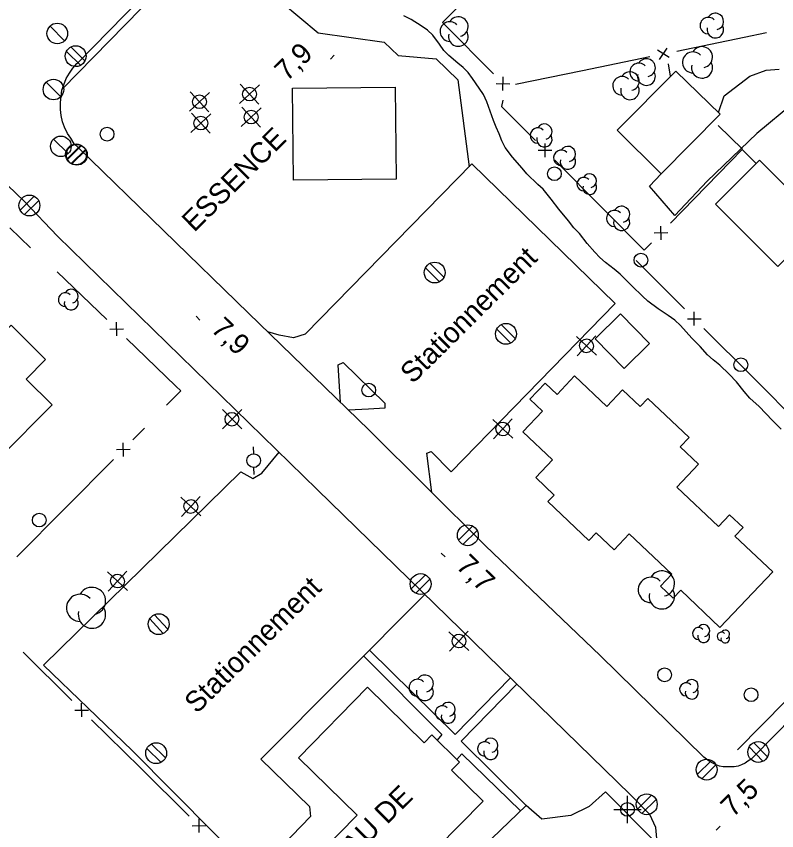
# Model space of a CAD drawing. Extents: x 381879 to 384696, y 5564785 to 5567594.
# Drawn here: x 382976.2 to 383086.9, y 5565460.7 to 5565579.4 of the extents above; entities that cross this region are included whole.
import ezdxf

# ---------------------------------------------------------------- set-up
doc = ezdxf.new("R2010")
doc.units = 0
for name, color, linetype in [('Niveau 19', 7, 'Continuous'), ('Niveau 2', 7, 'Continuous'), ('Niveau 21', 7, 'Continuous'), ('Niveau 22', 7, 'Continuous'), ('Niveau 3', 7, 'Continuous'), ('Niveau 31', 7, 'Continuous'), ('Niveau 36', 7, 'Continuous'), ('Niveau 37', 7, 'Continuous'), ('Niveau 44', 7, 'Continuous'), ('Niveau 52', 7, 'Continuous')]:
    doc.layers.add(name, color=color, linetype=linetype)

msp = doc.modelspace()

# ---------------------------------------------------------------- linework, layer by layer
at = {"layer": 'Niveau 19'}
for points in [[(383004.09, 5565590.45), (383020.14, 5565576.98), (383029.75, 5565575.6), (383031.78, 5565573.66), (383037.3, 5565573.18), (383040.47, 5565570.14), (383042.11, 5565557.46)], [(383078.43, 5565565.36), (383079.25, 5565567.78), (383082.99, 5565570.67), (383085.4, 5565571.55), (383087.27, 5565571.69)], [(383089.4, 5565566.79), (383084.03, 5565562.31), (383076.8, 5565555.33), (383072.08, 5565550.36), (383068.41, 5565554.6), (383070.1, 5565556.4)]]:
    msp.add_lwpolyline(points, dxfattribs=at)
at = {"layer": 'Niveau 2'}
msp.add_lwpolyline([(383087.58, 5565519.2), (383086.3, 5565520.48), (383084.35, 5565522.49), (383083, 5565523.74), (383082.17, 5565524.68), (383081.04, 5565526.09), (383079.99, 5565527.24), (383078.64, 5565528.53), (383077.64, 5565529.32), (383076.85, 5565530.05), (383075.75, 5565531.25), (383074.55, 5565532.49), (383072.89, 5565534.31), (383072.06, 5565535.07), (383071.12, 5565535.77), (383069.63, 5565536.74), (383068.15, 5565537.87), (383067.38, 5565538.58), (383065.87, 5565540.04), (383064.12, 5565541.79), (383063.24, 5565542.53), (383061.96, 5565543.5), (383061.16, 5565544.21), (383060.43, 5565544.99), (383059.31, 5565546.29), (383058.19, 5565547.71), (383057.39, 5565548.57), (383056.6, 5565549.56), (383055.17, 5565551.26), (383054.08, 5565552.72), (383052.92, 5565554.17), (383052.14, 5565554.89), (383050.53, 5565556.43), (383049.82, 5565557.23), (383048.43, 5565558.86), (383047.37, 5565560.24), (383046.88, 5565561.22), (383046.5, 5565562.26), (383046.05, 5565563.23), (383045.69, 5565564.21), (383044.7, 5565566.93), (383044.22, 5565568), (383043.56, 5565568.89), (383042.62, 5565570.31), (383041.98, 5565571.19), (383041.27, 5565571.94), (383040.48, 5565572.56), (383039.15, 5565573.69), (383038.44, 5565574.41), (383037.81, 5565575.31), (383036.82, 5565576.64), (383036.04, 5565577.38), (383035.13, 5565578), (383033.66, 5565578.94), (383032.61, 5565579.45)], dxfattribs=at)
at = {"layer": 'Niveau 21'}
for points in [[(382985.1, 5565572.6), (383001, 5565588.9), (383017.9, 5565606.2), (383037.5, 5565626.2), (383057, 5565646.4), (383075.1, 5565664.5), (383092, 5565682.1), (383100.4, 5565690.4)], [(382879.6, 5565647.04), (382958.64, 5565570.33), (382977.34, 5565552.41)], [(382985.2, 5565560.2), (382984.6, 5565560.8), (382984.1, 5565561.6), (382983.6, 5565562.3), (382983.2, 5565563.2), (382982.9, 5565564), (382982.7, 5565564.9), (382982.6, 5565565.8), (382982.6, 5565566.8), (382982.7, 5565567.7), (382982.8, 5565568.6), (382983.1, 5565569.4), (382983.4, 5565570.3), (382983.9, 5565571.1), (382984.4, 5565571.8), (382985, 5565572.5), (382985.1, 5565572.6)], [(383076.3, 5565471.4), (383061.2, 5565486.2), (383044.5, 5565502.2), (383027.5, 5565519.1), (383010, 5565536.1), (382985.2, 5565560.2)], [(383065.57, 5565453.03), (383068.81, 5565456.41), (383069.5, 5565458.99), (383069.32, 5565461.15), (383068.44, 5565463.02), (383065.61, 5565465.9), (383019.96, 5565510.43), (382982.18, 5565547.34), (382977.34, 5565552.41)], [(383105.1, 5565493.3), (383095.1, 5565483.2), (383083.6, 5565471.5)], [(383083.6, 5565471.5), (383083.2, 5565471.1), (383082.7, 5565470.8), (383082.3, 5565470.5), (383081.8, 5565470.3), (383081.3, 5565470.1), (383080.7, 5565470), (383080.2, 5565470), (383079.7, 5565470), (383079.1, 5565470), (383078.6, 5565470.1), (383078.1, 5565470.3), (383077.6, 5565470.5), (383077.1, 5565470.8), (383076.7, 5565471.1), (383076.3, 5565471.4)]]:
    msp.add_lwpolyline(points, dxfattribs=at)
at = {"layer": 'Niveau 22'}
for points in [[(383103.6, 5565691.84), (383085.8, 5565673.75), (383067.78, 5565655.57), (382982.85, 5565568.74)], [(383048.14, 5565482.94), (383040.06, 5565474.72), (383027.62, 5565486.99)], [(383026.76, 5565486.13), (383038.15, 5565474.71), (383037.44, 5565473.87)], [(383050.4, 5565464.35), (383040.96, 5565473.75), (383049.05, 5565482.05)], [(383040.32, 5565471.04), (383041.06, 5565471.89), (383049.61, 5565463.59)]]:
    msp.add_lwpolyline(points, dxfattribs=at)
at = {"layer": 'Niveau 3'}
for p, q in [((383021.91, 5565573.15), (383022.48, 5565573.72)), ((383002.34, 5565535.66), (383002.91, 5565535.09)), ((383038.05, 5565501.15), (383038.62, 5565500.59)), ((383078.09, 5565460.77), (383078.66, 5565461.34))]:
    msp.add_line(p, q, dxfattribs=at)
at = {"layer": 'Niveau 31'}
for points in [[(383072.2, 5565571.4), (383078.7, 5565565.1), (383070.1, 5565556.4), (383063.7, 5565562.8)], [(383016.4, 5565568.91), (383031.36, 5565569.05), (383031.49, 5565555.63), (383016.53, 5565555.49)], [(383078, 5565552), (383084.4, 5565558.4), (383093.5, 5565549.3), (383087.1, 5565542.9)], [(382957.38, 5565531.49), (382973.88, 5565515.19), (382981.36, 5565522.76), (382977.59, 5565526.49), (382980.43, 5565529.36), (382975.4, 5565534.34), (382972.07, 5565530.97), (382964.38, 5565538.57)], [(383064.72, 5565528.06), (383060.47, 5565532.35), (383064.15, 5565536), (383068.4, 5565531.71)], [(383063.25, 5565501.64), (383060.64, 5565504.1), (383059.56, 5565502.97), (383053.58, 5565508.64), (383054.49, 5565509.6), (383051.82, 5565512.14), (383054.27, 5565514.72), (383049.94, 5565518.84), (383052.79, 5565521.84), (383050.95, 5565523.58), (383053.18, 5565525.93), (383054.92, 5565524.28), (383057.48, 5565526.97), (383062.18, 5565522.51), (383064.47, 5565524.92), (383067.02, 5565522.5), (383068.14, 5565523.68), (383074.15, 5565517.97), (383072.87, 5565516.63), (383075.54, 5565514.1), (383072.37, 5565510.76), (383078.44, 5565505), (383080.06, 5565506.71), (383082.02, 5565504.86), (383080.84, 5565503.62), (383086.33, 5565498.41), (383078.63, 5565490.31), (383072.93, 5565495.72), (383071.83, 5565494.55), (383069.97, 5565496.3), (383071.64, 5565498.06), (383065.44, 5565503.95)], [(383027.32, 5565481.58), (383035.55, 5565473.49), (383036.67, 5565474.63), (383040.71, 5565470.66), (383039.57, 5565469.5), (383044.17, 5565464.98), (383034.08, 5565454.72), (383029.62, 5565459.11), (383028.96, 5565458.44), (383034.92, 5565452.57), (383032.45, 5565450.06), (383033.78, 5565448.75), (383031.69, 5565446.62), (383030.49, 5565447.79), (383024.03, 5565441.17), (383014.15, 5565450.82), (383018.48, 5565455.25), (383016.45, 5565457.23), (383018.61, 5565459.44), (383020.54, 5565457.55), (383025.8, 5565462.93), (383017.26, 5565471.28)]]:
    msp.add_lwpolyline(points, close=True, dxfattribs=at)
at = {"layer": 'Niveau 36'}
for p, q in [((382983.2, 5565575.82), (382981.08, 5565577.94)), ((382983.46, 5565574.24), (382985.54, 5565572.22)), ((382986.16, 5565572.9), (382984.08, 5565574.92)), ((382982.64, 5565567.65), (382980.52, 5565569.77)), ((383011.48, 5565566.57), (383008.76, 5565569.49)), ((383001.37, 5565565.56), (383004.29, 5565568.28)), ((383004.19, 5565565.46), (383001.47, 5565568.38)), ((383008.66, 5565566.67), (383011.58, 5565569.39)), ((383008.9, 5565563.32), (383011.82, 5565566.04)), ((383011.72, 5565563.22), (383009, 5565566.14)), ((383001.57, 5565562.44), (383004.49, 5565565.16)), ((383004.39, 5565562.34), (383001.67, 5565565.26)), ((382983.72, 5565559.37), (382981.6, 5565561.49)), ((382985.56, 5565560.59), (382983.5, 5565558.55)), ((382985.66, 5565560.54), (382983.6, 5565558.5)), ((382984.16, 5565557.91), (382986.22, 5565559.95)), ((382984.26, 5565557.86), (382986.32, 5565559.9)), ((382978.76, 5565553.15), (382976.7, 5565551.11)), ((382977.36, 5565550.47), (382979.42, 5565552.51)), ((383038.44, 5565541.35), (383036.39, 5565543.4)), ((383035.76, 5565542.73), (383037.81, 5565540.68)), ((383048.83, 5565532.41), (383046.76, 5565534.44)), ((383046.13, 5565533.77), (383048.2, 5565531.74)), ((383057.74, 5565532.71), (383060.65, 5565529.99)), ((383057.84, 5565529.9), (383060.56, 5565532.81)), ((383008.99, 5565522.05), (383006.17, 5565519.23)), ((383008.99, 5565519.23), (383006.17, 5565522.05)), ((383045.55, 5565520.59), (383048.46, 5565517.87)), ((383045.65, 5565517.78), (383048.37, 5565520.69)), ((383010.66, 5565516.62), (383010.71, 5565515.62)), ((383010.81, 5565512.62), (383010.77, 5565513.62)), ((383000.11, 5565509.29), (383003.02, 5565506.57)), ((383000.21, 5565506.48), (383002.93, 5565509.39)), ((383042.61, 5565505.08), (383040.55, 5565503.04)), ((383041.21, 5565502.4), (383043.27, 5565504.44)), ((382989.43, 5565498.42), (382992.34, 5565495.7)), ((382989.53, 5565495.61), (382992.25, 5565498.52)), ((383035.74, 5565497.97), (383033.68, 5565495.93)), ((383034.34, 5565495.29), (383036.4, 5565497.33)), ((382995.59, 5565491.55), (382997.54, 5565489.4)), ((382998.21, 5565490.03), (382996.26, 5565492.18)), ((383039.17, 5565489.68), (383042.08, 5565486.96)), ((383039.27, 5565486.87), (383041.99, 5565489.78)), ((382997.88, 5565471.3), (382995.82, 5565473.34)), ((383085.56, 5565471.44), (383083.56, 5565473.53)), ((382995.18, 5565472.68), (382997.24, 5565470.64)), ((383082.9, 5565472.88), (383084.9, 5565470.79)), ((383077.4, 5565470.92), (383075.34, 5565468.88)), ((383076, 5565468.24), (383078.06, 5565470.28)), ((383065.16, 5565461.79), (383065.18, 5565465.78)), ((383068.68, 5565465.87), (383066.62, 5565463.83)), ((383067.28, 5565463.19), (383069.34, 5565465.23)), ((383063.18, 5565463.79), (383067.16, 5565463.78))]:
    msp.add_line(p, q, dxfattribs=at)
for centre, radius in [((382982.13, 5565576.88), 1.5), ((382981.57, 5565568.71), 1.5), ((383010.13, 5565568.04), 1), ((383002.84, 5565566.93), 1), ((383003.04, 5565563.81), 1), ((383010.37, 5565564.69), 1), ((382989.39, 5565562.2), 1), ((382982.65, 5565560.43), 1.5), ((382984.87, 5565559.25), 1.52), ((382984.97, 5565559.2), 1.52), ((383054.54, 5565556.43), 1), ((382978.07, 5565551.81), 1.52), ((383067.14, 5565543.84), 1), ((383081.69, 5565528.6), 1), ((383027.49, 5565524.9), 1), ((383007.57, 5565520.64), 1), ((382979.51, 5565505.96), 1), ((383041.92, 5565503.74), 1.52), ((383035.05, 5565496.63), 1.52), ((383070.59, 5565483.4), 1), ((383083.19, 5565480.5), 1), ((383076.71, 5565469.58), 1.52), ((383067.99, 5565464.53), 1.52), ((383065.18, 5565463.79), 1)]:
    msp.add_circle(centre, radius, dxfattribs=at)
for centre, major_axis, ratio in [((382984.81, 5565573.58), (-0.01, -1.52), 0.999981), ((383037.1, 5565542.03), (0.01, 1.52), 0.999981), ((383047.48, 5565533.1), (-0.02, -1.52), 0.999984), ((383059.21, 5565531.35), (-0.048, -0.999), 0.999982), ((383047.02, 5565519.23), (-0.048, -0.999), 0.999982), ((383010.74, 5565514.63), (-0.05, -0.999), 0.999983), ((383001.58, 5565507.93), (-0.048, -0.999), 0.999982), ((382990.9, 5565497.06), (-0.048, -0.999), 0.999982), ((382996.9, 5565490.78), (0.02, 1.52), 0.999983), ((383040.64, 5565488.32), (-0.048, -0.999), 0.999982), ((382996.53, 5565471.98), (0.01, 1.52), 0.999981), ((383084.23, 5565472.15), (-0.01, -1.52), 0.999983)]:
    msp.add_ellipse(centre, major_axis=major_axis, ratio=ratio, dxfattribs=at)
at = {"layer": 'Niveau 37'}
for p, q in [((383071.24, 5565573.37), (383069.57, 5565574.47)), ((383069.86, 5565573.08), (383070.96, 5565574.75)), ((383046.05, 5565569.57), (383048.05, 5565569.55)), ((383047.04, 5565568.56), (383047.06, 5565570.56)), ((383053.18, 5565558.85), (383053.19, 5565560.85)), ((383052.18, 5565559.85), (383054.18, 5565559.85)), ((383070.08, 5565546.79), (383070.05, 5565548.79)), ((383071.06, 5565547.81), (383069.06, 5565547.78)), ((383074.91, 5565534.31), (383074.91, 5565536.31)), ((383073.91, 5565535.31), (383075.91, 5565535.31)), ((382990.79, 5565532.8), (382990.75, 5565534.8)), ((382989.77, 5565533.78), (382991.77, 5565533.82)), ((382991.75, 5565515.22), (382991.74, 5565517.22)), ((382992.74, 5565516.22), (382990.74, 5565516.21)), ((382985.7, 5565477.26), (382985.68, 5565479.26)), ((382984.69, 5565478.25), (382986.69, 5565478.27)), ((383001.78, 5565461.41), (383003.79, 5565461.42)), ((383002.79, 5565460.41), (383002.78, 5565462.41))]:
    msp.add_line(p, q, dxfattribs=at)
for points in [[(383044.91, 5565585.21), (383038.25, 5565578.5), (383038.63, 5565578.11)], [(383038.63, 5565578.11), (383045.65, 5565570.98)], [(383082.16, 5565576.34), (383085.43, 5565577.01)], [(383072.37, 5565574.32), (383082.16, 5565576.34)], [(383058.65, 5565571.5), (383068.45, 5565573.51)], [(383071.45, 5565570.64), (383071.16, 5565572.43)], [(383048.86, 5565569.48), (383058.65, 5565571.5)], [(383047.03, 5565567.18), (383046.84, 5565566.24), (383051.77, 5565561.27)], [(383078.43, 5565556.4), (383081.88, 5565559.95), (383081.95, 5565560.02), (383078.41, 5565563.47)], [(383081.88, 5565559.95), (383083.93, 5565557.93)], [(383054.59, 5565558.43), (383061.63, 5565551.33)], [(383071.46, 5565549.23), (383078.43, 5565556.4)], [(383061.63, 5565551.33), (383067.63, 5565545.29), (383068.67, 5565546.36)], [(382978.22, 5565545.64), (382975.22, 5565548.54)], [(383066.44, 5565543.81), (383073.5, 5565536.73)], [(382982.12, 5565542.12), (382989.33, 5565535.19)], [(383076.32, 5565533.9), (383083.38, 5565526.81)], [(382992.21, 5565532.41), (382999.41, 5565525.48)], [(383083.38, 5565526.81), (383090.44, 5565519.73)], [(382999.41, 5565525.48), (383000.14, 5565524.78), (382998.04, 5565522.72)], [(382993.15, 5565517.64), (382994.84, 5565519.34)], [(382983.29, 5565507.7), (382990.33, 5565514.8)], [(382976.25, 5565500.6), (382983.29, 5565507.7)], [(382977.14, 5565486.68), (382984.26, 5565479.66)], [(383081.21, 5565472.47), (383088.23, 5565479.59)], [(382987.11, 5565476.85), (382994.24, 5565469.84)], [(382994.24, 5565469.84), (383001.36, 5565462.82)]]:
    msp.add_lwpolyline(points, dxfattribs=at)
at = {"layer": 'Niveau 44'}
for centre, radius, start, end in [((383040.54, 5565577.88), 1.43, 282.2692, 149.7262), ((383076.95, 5565578.03), 1.2, 44.1153, 269.8039), ((383077.98, 5565578.63), 1.2, 282.2692, 149.7262), ((383039.31, 5565577.16), 1.43, 44.1153, 269.8039), ((383077.98, 5565577.43), 1.2, 166.9368, 29.6212), ((383040.54, 5565576.44), 1.43, 166.9368, 29.6212), ((383074.72, 5565572.66), 1.53, 44.1153, 269.8039), ((383076.04, 5565573.43), 1.53, 282.2692, 149.7262), ((383067.94, 5565571.9), 1.3, 282.2692, 149.7262), ((383066.83, 5565571.25), 1.3, 44.1153, 269.8039), ((383076.04, 5565571.9), 1.53, 166.9368, 29.6212), ((383065.54, 5565569.93), 1.35, 282.2692, 149.7262), ((383067.94, 5565570.61), 1.3, 166.9368, 29.6212), ((383064.38, 5565569.26), 1.35, 44.1153, 269.8039), ((383065.54, 5565568.58), 1.35, 166.9368, 29.6212), ((383053.08, 5565562.57), 1.12, 282.2692, 149.7262), ((383052.12, 5565562.01), 1.12, 44.1153, 269.8039), ((383053.08, 5565561.45), 1.12, 166.9368, 29.6212), ((383056.5, 5565559.31), 1.12, 282.2692, 149.7262), ((383055.54, 5565558.75), 1.12, 44.1153, 269.8039), ((383056.5, 5565558.19), 1.12, 166.9368, 29.6212), ((383059.68, 5565555.42), 1, 282.2692, 149.7262), ((383058.82, 5565554.92), 1, 44.1153, 269.8039), ((383059.68, 5565554.42), 1, 166.9368, 29.6212), ((383064.33, 5565550.52), 1.18, 282.2692, 149.7262), ((383063.31, 5565549.93), 1.18, 44.1153, 269.8039), ((383064.33, 5565549.34), 1.18, 166.9368, 29.6212), ((382983.3, 5565538.08), 1.01, 44.1153, 269.8039), ((382984.16, 5565538.59), 1.01, 282.2692, 149.7262), ((382984.16, 5565537.58), 1.01, 166.9368, 29.6212), ((383070.19, 5565496.7), 1.85, 282.2692, 149.7262), ((383068.6, 5565495.78), 1.85, 44.1153, 269.8039), ((382987.18, 5565494.16), 1.99, 282.2692, 149.7262), ((382985.47, 5565493.16), 1.99, 44.1153, 269.8039), ((383070.19, 5565494.85), 1.85, 166.9368, 29.6212), ((382987.18, 5565492.17), 1.99, 166.9368, 29.6212), ((383075.53, 5565489.42), 0.875, 44.1153, 269.8039), ((383076.28, 5565489.85), 0.875, 282.2692, 149.7262), ((383079.42, 5565489.3), 0.627, 282.2692, 149.7262), ((383076.28, 5565488.98), 0.875, 166.9368, 29.6212), ((383078.88, 5565488.99), 0.627, 44.1153, 269.8039), ((383079.42, 5565488.67), 0.627, 166.9368, 29.6212), ((383035.67, 5565482.13), 1.24, 282.2692, 149.7262), ((383034.6, 5565481.51), 1.24, 44.1153, 269.8039), ((383073.72, 5565481.28), 0.949, 44.1153, 269.8039), ((383074.54, 5565481.75), 0.949, 282.2692, 149.7262), ((383035.67, 5565480.89), 1.24, 166.9368, 29.6212), ((383074.54, 5565480.81), 0.949, 166.9368, 29.6212), ((383039.07, 5565478.37), 1.02, 282.2692, 149.7262), ((383038.19, 5565477.86), 1.02, 44.1153, 269.8039), ((383039.07, 5565477.35), 1.02, 166.9368, 29.6212), ((383044.38, 5565472.6), 1.04, 44.1153, 269.8039), ((383045.27, 5565473.13), 1.04, 282.2692, 149.7262), ((383045.27, 5565472.08), 1.04, 166.9368, 29.6212)]:
    msp.add_arc(centre, radius, start, end, dxfattribs=at)
at = {"layer": 'Niveau 52'}
for points in [[(383036.69, 5565509.96), (383035.94, 5565515.73), (383036.58, 5565515.96), (383039.5, 5565512.98), (383063.37, 5565537.5), (383042.52, 5565557.88), (383018.22, 5565533.03), (383016.52, 5565532.54), (383014.43, 5565532.91), (383012.81, 5565533.37)], [(383023.37, 5565523.11), (383023.02, 5565528.56), (383023.78, 5565528.92), (383029.86, 5565522.98), (383029.86, 5565522.28), (383027.48, 5565522.1), (383024.56, 5565521.96)], [(382993.05, 5565472.35), (382980.13, 5565484.81), (383008.88, 5565513.01), (383010.59, 5565512.01), (383011.91, 5565512.81), (383014.43, 5565515.83)], [(383035.68, 5565495.09), (383011.8, 5565471.09), (383018.87, 5565464.21), (383019, 5565462.75), (383010.91, 5565454.34), (382993.05, 5565472.35)], [(383068.93, 5565459.35), (383061.97, 5565466.32), (383059.62, 5565464.2), (383056.94, 5565462.89), (383052.73, 5565462.35), (383050.4, 5565464.35), (383025.45, 5565440.33), (383037.51, 5565428.41), (383050.11, 5565441.18), (383052.46, 5565441.91)]]:
    msp.add_lwpolyline(points, dxfattribs=at)

# ---------------------------------------------------------------- texts
at = {"layer": 'Niveau 3'}
for s, rotation, p in [('7,9', 44.7717, (383015.59, 5565569.77)), ('7,9  ', 316.2835, (383004.37, 5565533.62)), ('7,7  ', 316.034, (383040.06, 5565499.09)), ('7,5  ', 44.7717, (383080.55, 5565462.49))]:
    msp.add_text(s, height=3, rotation=rotation, dxfattribs=at).set_placement(p)
at = {"layer": 'Niveau 31'}
for s, p in [('ESSENCE', (383002.08, 5565547.82)), ('BUREAU DE', (383017.5, 5565448.95))]:
    msp.add_text(s, height=3, rotation=44.7717, dxfattribs=at).set_placement(p)
at = {"layer": 'Niveau 52'}
for p in [(383033.89, 5565525.7), (383002.46, 5565477.63)]:
    msp.add_text('Stationnement', height=3, rotation=44.7717, dxfattribs=at).set_placement(p)

doc.saveas('drawing.dxf')
